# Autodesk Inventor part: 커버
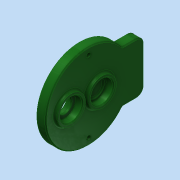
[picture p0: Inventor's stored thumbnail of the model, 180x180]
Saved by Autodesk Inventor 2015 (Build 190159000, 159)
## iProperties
Created: 2016-02
Part Number: 커버
Material: 알루미늄 6061
Document SubType Name: Modeling
Designer: mduedu
Density: 2.71 g/cm^3
Appearance: 매끄러움 - 짙은 산림 녹색
Mass: 157.248 g
Surface Area: 178.476 cm^2
Volume: 58.0249 cm^3
Author: mduedu
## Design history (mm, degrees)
sketch "스케치1"
  geometry: C1 r 43 at (0, 0); 1 further point
  constraints: 1 centre point, 1 coincident
  dimensions: "d0" = 86 diameter of C1
extrude "돌출1" new body sketch "스케치1" distance "d1" = 9; taper "d2" = 0 deg
sketch "스케치2"
  geometry: C1 r 14 at (0, 11); 1 further point
  constraints: 1 centre point, 1 vertical alignment
  dimensions: "d3" = 28 diameter of C1; "d6" = 11 distance of C1.centre point (0, 0)
extrude "돌출2" join sketch "스케치2" distance "d7" = 3; taper "d8" = 0 deg
sketch "스케치3"
  geometry: C1 r 14 at (0, -20); 1 further point
  constraints: 1 centre point, 1 vertical alignment
  dimensions: "d9" = 28 diameter of C1; "d10" = 20 distance of C1.centre point (0, 0)
extrude "돌출3" join sketch "스케치3" distance "d11" = 3; taper "d12" = 0 deg
hole "구멍1" diameter "d15" = 22; stored, may be unused: countersink angle "d19" = 90 deg, drill point angle "d21" = 0 deg; dims "d13" = 10, "d14" = 10, "d16" = 6, "d17" = 4, "d18" = 2, "d20" = 7
hole "구멍2" diameter "d24" = 18; stored, may be unused: countersink angle "d28" = 90 deg, drill point angle "d30" = 0 deg; dims "d22" = 10, "d23" = 10, "d25" = 6, "d26" = 4, "d27" = 2, "d29" = 1
hole "구멍3" diameter "d33" = 22; stored, may be unused: countersink angle "d37" = 90 deg, drill point angle "d39" = 0 deg; dims "d34" = 6, "d35" = 4, "d36" = 2, "d38" = 7, "d73" = 10, "d74" = 10
sketch "스케치7"
  geometry: L1 (-26, 34.249)-(26, 34.249); L2 (26, 34.249)-(26, 56); L3 (26, 56)-(-26, 56); L4 (-26, 56)-(-26, 34.249); A1 r 43 centre (0, 0) between (-26, 34.249) and (26, 34.249) reference; 1 further point
  constraints: 8 end point, 2 parallel, 2 point on circle, 1 horizontal, 1 perpendicular
  dimensions: "d95" = 52 distance of L2.end L3.end; "d97" = 56 distance from line of L3 point (0, 0)
extrude "돌출5" join sketch "스케치7" stored distance "d98" = 10; taper "d99" = 0 deg
sketch "스케치4"
  geometry: C1 r 14 at (0, -20) reference; C2 r 18 at (0, -20); 1 further point
  constraints: 1 centre point, 1 coincident
  dimensions: "d40" = 36 diameter of C2
extrude "돌출4" join sketch "스케치4" distance "d41" = 4; taper "d42" = 0 deg
hole "구멍4" diameter "d45" = 22; stored, may be unused: countersink angle "d49" = 90 deg, drill point angle "d51" = 0 deg; dims "d43" = 10, "d44" = 10, "d46" = 6, "d47" = 4, "d48" = 2, "d50" = 7
hole "구멍5" diameter "d54" = 15; stored, may be unused: countersink angle "d58" = 90 deg, drill point angle "d60" = 0 deg; dims "d52" = 10, "d53" = 10, "d55" = 6, "d56" = 4, "d57" = 2, "d59" = 7
fillet "모깎기1" dims "d61" = 0.3
fillet "모깎기2" dims "d62" = 2
chamfer "모따기1" distance "d63" = 1; stored, may be unused: second distance "d64" = 2, angle "d65" = 45 deg
fillet "모깎기6" dims "d88" = 2
sketch "스케치5" dims "d67" = 72
  geometry: 4 further points
  constraints: 2 horizontal alignment, 1 coincident, 5 other
  dimensions: "d71" = 360 deg dimension on point (0, 0) point (-36, 0) (derived)
fillet "모깎기4" dims "d75" = 2
sketch "스케치6"
  geometry: 2 further points
hole "구멍6" sketch "스케치6" at (36, 0), (-36, 0) diameter "d76" = 4.5; stored, may be unused: countersink angle "d80" = 90 deg, drill point angle "d82" = 0 deg; dims "d77" = 6, "d78" = 8, "d79" = 4.6, "d81" = 8
fillet "모깎기7" dims "d100" = 8, "d101" = 2
chamfer "모따기2" distance "d90" = 1; stored, may be unused: second distance "d91" = 2, angle "d92" = 45 deg
node "솔리드1"
node "절단 모서리 투영1"
